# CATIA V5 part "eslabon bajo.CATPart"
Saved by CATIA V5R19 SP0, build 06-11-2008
Part number: eslabon bajo
Material "Dull Blue": density 7860 kg/m3, Young's modulus 2e+11 Pa, Poisson ratio 0.266
Bounding box of the stored display mesh (mm): x 215.134 to 253.234, y -367.3 to 363.3, z 11055.686 to 11290.485
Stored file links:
  E:\Luis\Dropbox\3DIT\Parking\planos\cat 3 dit park8\eslabon bajo.CATPart
  E:\Luis\Dropbox\3DIT\Parking\planos\cat 3 dit park8\Eslabon de Cadena.........................................CATProduct
  E:\Luis\Dropbox\3DIT\Parking\planos\cat 3 dit park8\ensamble unico eslabon.CATProduct
  E:\Luis\Dropbox\3DIT\Parking\planos\cat 3 dit park8\Eslabon Bajo Completo.CATProduct
  E:\Luis\Dropbox\3DIT\Parking\planos\cat 3 dit park8\EslabonCompleto.CATProduct
  C:\Program Files (x86)\Dassault Systemes\B19\intel_a\startup\materials\Catalog.CATMaterial
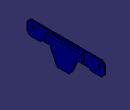
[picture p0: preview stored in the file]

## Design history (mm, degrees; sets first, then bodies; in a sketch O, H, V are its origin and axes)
External parameters (linked from other documents)
  External.p = 625
  External.b1 = 38.1
  External.b2 = 50.8
  External.d2 = 26.4
  External.g = 50.8
Body1 (main body), material "Dull Blue"
  DatumSurface1
  DatumCurve1 to DatumCurve18
  Sketch1 on face of DatumSurface1, origin (253.2342, 0, 0), H (0, -1, 0), V (0, 0, 1)
    line L1 (2, 11290.4854) -> (367.3, 11290.4854)
    line L2 (367.3, 11290.4854) -> (367.3, 11158.4854)
    line L3 (235.3, 11175.6854) -> (2, 11175.6854)
    point P1 (367.3, 11290.4854)
    point P2 (367.3, 11158.4854)
    line L4 (235.3, 11175.6854) -> (235.3, 11158.4854)
    line L5 (235.3, 11158.4854) -> (367.3, 11158.4854)
    line L6 (367.3, 11158.4854) -> (367.3, 11158.4854)
    point P3 (235.3, 11158.4854)
    point P4 (367.3, 11158.4854)
    construction line L7 (367.3, 11290.4854) -> (235.3, 11158.4854)
    point P5 (235.3, 11175.6854)
    construction line L8 (2, 11290.4854) -> (2, 11078.9054)
    point P6 (2, 11290.4854)
    point P8 (2, 11175.6854)
    point P9 (-363.3, 11290.4854)
    point P10 (-363.3, 11158.4854)
    point P11 (-231.3, 11158.4854)
    point P12 (-363.3, 11158.4854)
    construction line L9 (-363.3, 11290.4854) -> (-231.3, 11158.4854)
    point P13 (-231.3, 11175.6854)
    point P14 (2, 11290.4854)
    point P15 (2, 11175.6854)
    line L10 (2, 11290.4854) -> (-363.3, 11290.4854)
    line L11 (-363.3, 11290.4854) -> (-363.3, 11158.4854)
    line L12 (-231.3, 11175.6854) -> (2, 11175.6854)
    line L13 (-231.3, 11175.6854) -> (-231.3, 11158.4854)
    line L14 (-231.3, 11158.4854) -> (-363.3, 11158.4854)
    line L15 (-363.3, 11158.4854) -> (-363.3, 11158.4854)
    circle A1 centre (-310.5, 11239.6854) radius 13.2
    circle A2 centre (314.5, 11239.6854) radius 13.2
    point P16 (-310.5, 11239.6854)
    point P17 (314.5, 11239.6854)
    construction line L16 (314.5, 11239.6854) -> (-310.5, 11239.6854)
    radius A2 = 13.2 {= External.d2 /2000}
    distance A2 L2 = 39.6 {= Sketch1.distance(L11 A1)}
    distance A1 L3 = 50.8 {= Sketch1.distance(P17 L1)}
    angle L7 L5 = 45
    length L5 = 132 {= External.d2 *5/1000}
    length L11 = 132 {= Sketch1.length(L5)}
    distance L11 A1 = 39.6 {= External.d2 *1.5/1000}
    radius A1 = 13.2 {= External.d2/2 /1000}
    distance P16 L8 = 312.5 {= External.p /2000}
    distance P2 H = 11158.4854
    distance L11 V = 363.3
    distance P17 L8 = 312.5 (reference)
    distance P17 L1 = 50.8 {= External.g /1000}
    horizontal: L1 H, L3 H, L5 H, L16 H
    vertical: L2 V, L4 V, L6 V, L8 V
    coincidence: L8 P8
    symmetry: P1 P9 L8, P2 P10 L8, P3 P11 L8, P4 P12 L8, L7 L9 L8, P5 P13 L8, P6 P14 L8, P8 P15 L8, L1 L10 L8, L2 L11 L8, L3 L12 L8, L4 L13 L8, L5 L14 L8, L6 L15 L8
    concentricity: P16 A1, P17 A2
  Pad1: profile Sketch1, direction (-1, 0, 0), length 38.1, opposite side length -25.4
  DatumCurve19 to DatumCurve31
  Sketch2 on start face of Pad1, origin (227.8342, 0, 0), H (0, 1, 0), V (0, 0, 1)
    point P1 (0, 11055.6854)
    line L1 (0, 11055.6854) -> (60, 11055.6854)
    point P2 (60, 11055.6854)
    line L2 (60, 11055.6854) -> (120.9802, 11188.7304)
    point P3 (115, 11175.6829)
    line L3 (120.9802, 11188.7304) -> (120.9802, 11271.4354)
    point P4 (120.9802, 11271.4354)
    line L4 (120.9802, 11271.4354) -> (0, 11271.4354)
    point P5 (0, 11271.4354)
    construction line L5 (0, 11463.76) -> (0, 11058.4)
    point P6 (0, 11463.76)
    reference projected line E1 (-273.1, 11290.4854) -> (273.1, 11290.4854) from edge [start face of Pad1 | face of Pad1 from Sketch1.L1]
    reference projected line E2 (-593.6177, 11109.2854) -> (-745.0129, 11109.2854) from edge of DatumCurve19
    reference projected line E3 (-832.0978, 10989.2854) -> (-876.0554, 10989.2854) from edge of DatumCurve20
    reference projected line E4 (273.1, 11175.6854) -> (-273.1, 11175.6854) from edge [start face of Pad1 | face of Pad1 from Sketch1.L3]
    reference projected arc E5 centre (-1007.0978, 11084.2854) radius 25 from (-984.3712, 11094.7017) to (-1007.0978, 11109.2854) ccw from edge of DatumCurve23
    reference projected arc E6 centre (-745.0129, 11084.2854) radius 25 from (-745.0129, 11109.2854) to (-767.7395, 11094.7017) ccw from edge of DatumCurve24
    point P12 (-745.0129, 11084.2854)
    point P13 (-1007.0978, 11084.2854)
    reference projected line E7 (-767.7395, 11094.7017) -> (-809.3712, 11003.869) from edge of DatumCurve25
    reference projected line E8 (-593.6177, 11109.2854) -> (-745.0129, 11109.2854) from edge of DatumCurve26
    reference projected line E9 (-942.7395, 11003.869) -> (-984.3712, 11094.7017) from edge of DatumCurve27
    reference projected line E10 (-1007.0978, 11109.2854) -> (-1158.4931, 11109.2854) from edge of DatumCurve28
    construction line L6 (-809.3712, 11003.869) -> (-730.157, 11176.7)
    point P22 (-730.157, 11176.7)
    construction line L7 (-637.19, 11109.2854) -> (-761.0554, 11109.2854)
    point P23 (-637.19, 11109.2854)
    construction line L8 (-1092.08, 11109.2854) -> (-991.0554, 11109.2854)
    point P24 (-1092.08, 11109.2854)
    construction line L9 (-966.4887, 11055.6854) -> (-1023.0996, 11179.2)
    point P25 (-966.4887, 11055.6854)
    point P27 (-761.0554, 11109.2854)
    point P28 (-991.0554, 11109.2854)
    reference projected line E11 (-832.0978, 10989.2854) -> (-876.0554, 10989.2854) from edge of DatumCurve29
    construction line L10 (-1019.9583, 11172.3462) -> (-916.076, 10945.6939)
    point P29 (-1019.9583, 11172.3462)
    construction line L11 (-788.5554, 11049.2854) -> (-845.87, 10950.31)
    point P31 (-788.5554, 11049.2854)
    construction line L12 (-788.5554, 11049.2854) -> (-836.0348, 10945.6939)
    point P33 (-836.0348, 10945.6939)
    construction line L13 (-836.0348, 10945.6939) -> (-916.076, 10945.6939)
    point P34 (-836.0348, 10945.6939)
    reference projected line E12 (-832.0978, 10989.2854) -> (-876.0554, 10989.2854) from edge of DatumCurve30
    construction line L14 (-974.5584, 10989.2854) -> (-936.0554, 10989.2854)
    point P37 (-974.5584, 10989.2854)
    point P38 (-936.0554, 10989.2854)
    construction line L15 (-876.0554, 10989.2854) -> (-816.0554, 10989.2854)
    point P39 (-816.0554, 10989.2854)
    reference projected circle E13 centre (-641.0554, 11209.2854) radius 12.7 from edge of DatumCurve31
    point P40 (-641.0554, 11209.2854)
    reference projected circle E14 centre (-314.5, 11239.6854) radius 13.2 from edge [face of Pad1 from Sketch1.A2 | start face of Pad1]
    point P41 (-314.5, 11239.6854)
    point P42 (0, 11271.4354)
    point P43 (-120.9802, 11271.4354)
    line L16 (-120.9802, 11271.4354) -> (0, 11271.4354)
    line L17 (-120.9802, 11188.7304) -> (-120.9802, 11271.4354)
    point P44 (-115, 11175.6829)
    point P45 (-60, 11055.6854)
    line L18 (-60, 11055.6854) -> (-120.9802, 11188.7304)
    point P46 (0, 11055.6854)
    line L19 (0, 11055.6854) -> (-60, 11055.6854)
    point P48 (120.9802, 11188.7304)
    reference projected line E15 (-273.1, 11290.4854) -> (273.1, 11290.4854) from edge [start face of Pad1 | face of Pad1 from Sketch1.L1]
    reference projected line E16 (285.8, 11158.4854) -> (167.8, 11158.4854) from edge [start face of Pad1 | face of Pad1 from Sketch1.L14]
    distance L4 E1 = 19.05
    distance E2 E3 = 120 (reference)
    distance E4 L1 = 120
    distance P27 E11 = 120 (reference)
    distance P28 P27 = 230 (reference)
    distance P3 L5 = 115
    distance P39 P38 = 120 (reference)
    length L1 = 60
    distance P40 L7 = 100
    distance P48 E15 = 101.7549
    angle L6 L7 = 114.6236 (reference)
    angle L2 E16 = 114.624
    coincidence: P1 V, P6 V, P5 L5, P22 E7, P23 E8, P24 E10, P25 L1, P25 E9, L6 P27, L9 P28, P29 E9, P34 P33, L10 E9, P37 E12, L10 P38, L14 L15, L12 P39, P44 L18, P3 L2, P1 P46, P5 P42
    horizontal: L1 H, L4 H, L13 H, L14 H, L15 H
    vertical: L3 V, L5 V
    concentricity: P12 E6, P13 E5, P40 E13, P41 E14
    tangency: L7 E5, L8 E6, L9 E5, L10 E5, L12 E6
    midpoint: P31 E7
    symmetry: P5 P42 L5, P4 P43 L5, L4 L16 L5, L3 L17 L5, P3 P44 L5, P2 P45 L5, L2 L18 L5, P1 P46 L5, L1 L19 L5
  Pad2: profile Sketch2, direction (1, 0, 0), length 25.4
  Sketch3 on end face of Pad2, origin (253.2342, 0, 0), H (0, 1, 0), V (0, 0, 1)
    line L1 (170.9802, 11271.4354) -> (-170.9802, 11271.4354)
    line L2 (-170.9802, 11271.4354) -> (-170.9802, 11201.0854)
    line L3 (-170.9802, 11201.0854) -> (170.9802, 11201.0854)
    line L4 (170.9802, 11201.0854) -> (170.9802, 11271.4354)
    reference projected line E1 (114.9301, 11271.4354) -> (0, 11271.4354) from edge [face of Pad2 from Sketch2.L4 | end face of Pad2]
    reference projected line E2 (120.9802, 11158.3304) -> (120.9802, 11241.0354) from edge [face of Pad2 from Sketch2.L3 | end face of Pad2]
    reference projected line E3 (-120.9802, 11241.0354) -> (-120.9802, 11158.3304) from edge [face of Pad2 from Sketch2.L17 | end face of Pad2]
    reference projected line E4 (0, 11175.6854) -> (-167.8, 11175.6854) from edge [start face of Pad1 | face of Pad1 from Sketch1.L3]
    distance L1 E1 = 0
    distance L4 E2 = 50
    distance L2 E3 = 50
    distance L3 E4 = 25.4
    horizontal: L1 H, L3 H
    vertical: L2 V, L4 V
  Pad3: profile Sketch3, direction (1, 0, 0), up to start face of Pad1
  Chamfer1: length 26.4 {= External.d2 /1000}, angle 45, on edge [face of Pad1 from Sketch1.L1 | face of Pad1 from Sketch1.L2]; edge [face of Pad1 from Sketch1.L11 | face of Pad1 from Sketch1.L10]; edge [face of Pad1 from Sketch1.L2 | face of Pad1 from Sketch1.L5]; edge [face of Pad1 from Sketch1.L14 | face of Pad1 from Sketch1.L11]
  Chamfer2: length 6.6 {= External.d2 /4000}, angle 45, on edge [face of Pad1 from Sketch1.L5 | face of Pad1 from Sketch1.L4]; edge [face of Pad1 from Sketch1.L13 | face of Pad1 from Sketch1.L14]
  DatumSurface2
  Fillet1: radius 25, on edge [face of Pad2 from Sketch2.L19 | face of Pad2 from Sketch2.L18]; edge [face of Pad2 from Sketch2.L2 | face of Pad2 from Sketch2.L1]
  DatumSurface3
  DatumSurface4
  Sketch4 on DatumSurface4, origin (265.9342, -1.3635, 0.5939), H (0, -1, 0), V (0, 0, 1)
    reference projected curve E1 from edge [end face of Pad1 | face of Pad1 from Sketch1.A2]
    construction line L1 (324.9039, 11232.9924) -> (324.9039, 11232.9924)
    point P1 (324.9039, 11232.9924)
    point P2 (324.9039, 11232.9924)
    construction line L2 (324.8873, 11232.9607) -> (324.8873, 11232.9607)
    point P3 (324.8873, 11232.9607)
    point P4 (324.8873, 11232.9607)
    construction line L3 (324.9039, 11232.9924) -> (364.5556, 11243.79)
    point P5 (324.9039, 11232.9924)
    point P7 (324.9039, 11232.9924)
    coincidence: P1 E1, P2 E1, P3 E1, P4 E1, P7 P5
    vertical: L1 V
    horizontal: L2 H
    midpoint: P5 L1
